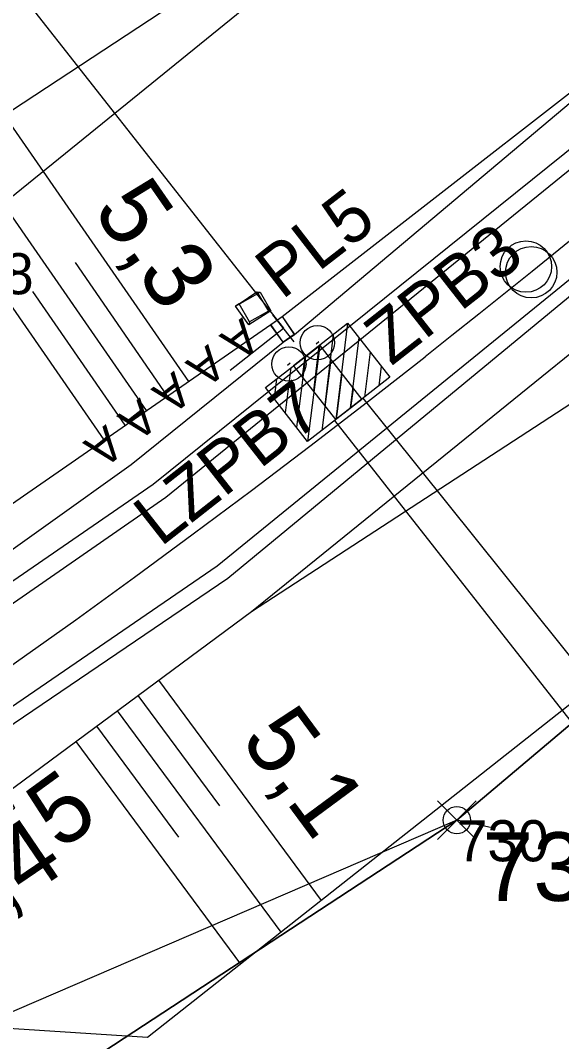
# Model space of a CAD drawing. Extents: x -800194 to -799078, y -1007177 to -1006597.
# Drawn here: x -799482.23 to -799466.45, y -1006953.32 to -1006923.53 of the extents above; entities that cross this region are included whole.
import ezdxf

# ---------------------------------------------------------------- set-up
doc = ezdxf.new("R2010")
doc.units = 0
for name, color, linetype in [('02_Osa_koleje', 7, 'Continuous'), ('_Vrstva 7 - Přesunutá', 7, 'Continuous'), ('Obvod stavby', 7, 'Continuous'), ('Vrstva 11', 7, 'Continuous'), ('Vrstva 12', 7, 'Continuous'), ('Vrstva 13', 7, 'Continuous'), ('Vrstva 27', 7, 'Continuous'), ('Vrstva 3', 7, 'Continuous'), ('Vrstva 4', 7, 'Continuous'), ('Vrstva 48', 7, 'Continuous'), ('Vrstva 49', 7, 'Continuous'), ('Vrstva 53', 7, 'Continuous'), ('Vrstva 55', 7, 'Continuous'), ('Vrstva 56', 7, 'Continuous'), ('Vrstva 6', 7, 'Continuous'), ('Vrstva 60', 7, 'Continuous'), ('Vrstva 7', 7, 'Continuous')]:
    doc.layers.add(name, color=color, linetype=linetype)

msp = doc.modelspace()

# ---------------------------------------------------------------- linework, layer by layer
at = {"layer": '02_Osa_koleje'}
msp.add_lwpolyline([(-799465.749, -1006929.588), (-799466.523, -1006930.22), (-799467.3, -1006930.85), (-799468.078, -1006931.478), (-799468.859, -1006932.103), (-799469.642, -1006932.726), (-799470.426, -1006933.345)], dxfattribs=at)
msp.add_arc((-799651.022, -1006703.891), 292, 255.62486, 308.20516, dxfattribs=at)
at = {"layer": '_Vrstva 7 - Přesunutá'}
msp.add_circle((-799467.33, -1006930.875), 0.75, dxfattribs=at)
at = {"layer": 'Obvod stavby'}
for p, q in [((-799470.066, -1006947.426), (-799468.934, -1006946.294)), ((-799470.066, -1006946.294), (-799468.934, -1006947.426))]:
    msp.add_line(p, q, dxfattribs=at)
msp.add_lwpolyline([(-799559.64, -1006968.48), (-799519.68, -1006952.01), (-799500.87, -1006940.41), (-799496.64, -1006937.8), (-799494.85, -1006936.7), (-799484.52, -1006930.32), (-799457.99, -1006908.8), (-799435, -1006885.17), (-799430.26, -1006880.27), (-799425.53, -1006875.38), (-799422.55, -1006864.36), (-799416.748, -1006858.798), (-799395.763, -1006879.374), (-799413.75, -1006898.23), (-799418.41, -1006902.53), (-799423.07, -1006906.83), (-799433.4, -1006916.39), (-799469.5, -1006946.86), (-799487.22, -1006958.47), (-799495.25, -1006963.74), (-799521.98, -1006977.8), (-799546.71, -1006987.83)], dxfattribs=at)
msp.add_circle((-799469.5, -1006946.86), 0.4, dxfattribs=at)
at = {"layer": 'Vrstva 12'}
for p, q in [((-799475.329, -1006931.448), (-799475.236, -1006931.455)), ((-799475.848, -1006931.802), (-799475.952, -1006931.866)), ((-799474.922, -1006932.004), (-799474.993, -1006932.013)), ((-799475.551, -1006932.322), (-799475.567, -1006932.408)), ((-799474.93, -1006932.406), (-799474.926, -1006932.405)), ((-799474.599, -1006932.171), (-799474.596, -1006932.171)), ((-799474.241, -1006932.695), (-799474.237, -1006932.694)), ((-799474.57, -1006932.917), (-799474.568, -1006932.916))]:
    msp.add_line(p, q, dxfattribs=at)
for points in [[(-799475.236, -1006931.455), (-799474.922, -1006932.004), (-799475.567, -1006932.408), (-799475.952, -1006931.866), (-799475.236, -1006931.455)], [(-799475.329, -1006931.448), (-799474.993, -1006932.013), (-799475.551, -1006932.322), (-799475.848, -1006931.802), (-799475.329, -1006931.448)], [(-799474.599, -1006932.171), (-799474.241, -1006932.695), (-799474.57, -1006932.917), (-799474.93, -1006932.406), (-799474.599, -1006932.171)], [(-799474.596, -1006932.171), (-799474.237, -1006932.694), (-799474.568, -1006932.916), (-799474.926, -1006932.405), (-799474.596, -1006932.171)]]:
    msp.add_lwpolyline(points, dxfattribs=at)
at = {"layer": 'Vrstva 27'}
for p, q in [((-799473.605, -1006932.963), (-799473.527, -1006932.901)), ((-799474.438, -1006933.585), (-799474.36, -1006933.523))]:
    msp.add_line(p, q, dxfattribs=at)
for centre in [(-799473.566, -1006932.932), (-799474.399, -1006933.554)]:
    msp.add_circle(centre, 0.5, dxfattribs=at)
at = {"layer": 'Vrstva 3'}
for p, q in [((-799472.686, -1006932.363), (-799473.025, -1006935.171)), ((-799473.103, -1006932.691), (-799473.352, -1006934.755)), ((-799473.499, -1006933.01), (-799473.857, -1006935.816)), ((-799473.521, -1006933.019), (-799473.68, -1006934.337)), ((-799472.359, -1006932.78), (-799472.608, -1006934.844)), ((-799473.918, -1006933.335), (-799474.181, -1006935.397)), ((-799472.031, -1006933.198), (-799472.19, -1006934.516)), ((-799473.938, -1006933.346), (-799474.007, -1006933.92)), ((-799473.175, -1006933.429), (-799473.438, -1006935.492)), ((-799471.704, -1006933.615), (-799471.773, -1006934.189)), ((-799474.338, -1006933.659), (-799474.506, -1006934.977)), ((-799472.85, -1006933.849), (-799473.018, -1006935.167)), ((-799474.757, -1006933.984), (-799474.83, -1006934.557)), ((-799472.525, -1006934.269), (-799472.599, -1006934.842)), ((-799442.19, -1006974.528), (-799473.063, -1006935.201))]:
    msp.add_line(p, q, dxfattribs=at)
for points in [[(-799471.451, -1006933.937), (-799473.025, -1006935.171), (-799474.26, -1006933.598), (-799472.686, -1006932.363)], [(-799472.275, -1006934.592), (-799473.857, -1006935.816), (-799475.081, -1006934.234), (-799473.499, -1006933.01)]]:
    msp.add_lwpolyline(points, close=True, dxfattribs=at)
msp.add_lwpolyline([(-799439.356, -1006972.379), (-799450.062, -1006959.03), (-799451.608, -1006960.27), (-799472.235, -1006934.552)], dxfattribs=at)
at = {"layer": 'Vrstva 4'}
for points in [[(-799510.394, -1006958.536), (-799498.027, -1006951.328), (-799477.988, -1006937.435), (-799460.33, -1006923.117), (-799451.862, -1006915.581), (-799443.604, -1006907.9), (-799435.444, -1006900.067), (-799428.64, -1006893.299), (-799422.817, -1006887.511), (-799415.998, -1006880.595), (-799408.158, -1006872.652), (-799401.02, -1006864.85)], [(-799509.248, -1006960.724), (-799497.456, -1006953.809), (-799476.495, -1006939.437), (-799458.707, -1006924.982), (-799450.277, -1006917.43), (-799441.932, -1006909.717), (-799433.783, -1006901.867), (-799426.9, -1006895.092), (-799421.037, -1006889.182), (-799414.218, -1006882.281), (-799406.443, -1006874.417), (-799398.609, -1006866.93)], [(-799511.236, -1006957.129), (-799499.236, -1006950.771), (-799498.598, -1006949.914), (-799498.679, -1006949.705), (-799496.151, -1006948.479), (-799496.251, -1006948.258), (-799490.687, -1006944.683), (-799490.497, -1006944.878), (-799488.249, -1006943.052), (-799488.105, -1006943.216), (-799486.269, -1006941.68), (-799478.997, -1006936.484), (-799474.568, -1006932.916), (-799474.237, -1006932.694), (-799461.519, -1006921.99), (-799452.935, -1006914.372), (-799444.695, -1006906.886), (-799436.579, -1006898.932), (-799429.629, -1006892.192), (-799429.07, -1006892.727), (-799423.479, -1006886.901), (-799416.56, -1006880.007), (-799417.085, -1006879.46), (-799415.349, -1006878.386)], [(-799510.726, -1006958.045), (-799497.901, -1006950.516), (-799478.36, -1006937.055), (-799461.534, -1006923.53), (-799452.128, -1006915.305), (-799443.894, -1006907.632), (-799435.739, -1006899.754), (-799428.922, -1006893.007), (-799423.223, -1006887.256), (-799416.277, -1006880.269), (-799414.896, -1006878.87)], [(-799509.087, -1006961.127), (-799497.277, -1006954.118), (-799476.183, -1006939.802), (-799458.586, -1006925.284), (-799449.914, -1006917.869), (-799441.499, -1006910.139), (-799433.371, -1006902.28), (-799426.451, -1006895.478), (-799420.657, -1006889.585), (-799413.85, -1006882.742), (-799412.388, -1006881.287)], [(-799507.817, -1006962.779), (-799497.104, -1006956.83), (-799497.4, -1006955.599), (-799497.585, -1006955.395), (-799495.628, -1006953.965), (-799495.505, -1006954.146), (-799493.236, -1006952.753), (-799493.081, -1006952.976), (-799487.499, -1006949.378), (-799487.565, -1006949.124), (-799485.713, -1006947.881), (-799485.847, -1006947.698), (-799483.858, -1006946.36), (-799483.734, -1006946.536), (-799483.686, -1006946.569), (-799482.647, -1006946.068), (-799475.489, -1006940.774), (-799457.684, -1006926.366)]]:
    msp.add_lwpolyline(points, dxfattribs=at)
at = {"layer": 'Vrstva 48'}
for p, q in [((-799477.319, -1006934.06), (-799482.69, -1006926.295)), ((-799478.552, -1006934.913), (-799483.943, -1006927.119)), ((-799479.786, -1006935.767), (-799485.197, -1006927.943)), ((-799477.935, -1006934.487), (-799480.626, -1006930.597)), ((-799479.169, -1006935.34), (-799481.87, -1006931.436)), ((-799478.201, -1006942.78), (-799473.453, -1006949.2)), ((-799478.804, -1006943.226), (-799476.423, -1006946.446)), ((-799479.407, -1006943.672), (-799474.631, -1006950.13)), ((-799480.01, -1006944.118), (-799477.616, -1006947.356)), ((-799480.613, -1006944.564), (-799475.81, -1006951.059))]:
    msp.add_line(p, q, dxfattribs=at)
at = {"layer": 'Vrstva 49'}
for points in [[(-799429.125, -1006891.656), (-799433.133, -1006889.484), (-799437.572, -1006888.963), (-799439.693, -1006890.332), (-799461.15, -1006912.135), (-799487.142, -1006929.222), (-799487.006, -1006931.546), (-799490.308, -1006935.771)], [(-799490.09, -1006944.145), (-799488.194, -1006942.597), (-799488.011, -1006942.815), (-799488.011, -1006942.815), (-799486.419, -1006941.508), (-799486.269, -1006941.68), (-799484.618, -1006939.109), (-799474.926, -1006932.405), (-799474.596, -1006932.171), (-799461.519, -1006921.99), (-799452.935, -1006914.372), (-799445.566, -1006906.106), (-799432.588, -1006892.596), (-799429.125, -1006891.656)], [(-799486.865, -1006949.018), (-799484.86, -1006947.727), (-799485.016, -1006947.459), (-799485.713, -1006947.881), (-799483.734, -1006946.536), (-799483.686, -1006946.569), (-799483.396, -1006947.063), (-799482.389, -1006946.51), (-799482.647, -1006946.068), (-799475.489, -1006940.774), (-799464.892, -1006933.871), (-799456.989, -1006927.138), (-799455.117, -1006925.642), (-799440.165, -1006911.165), (-799428.918, -1006899.95), (-799428.299, -1006900.544), (-799427.466, -1006899.73), (-799428.131, -1006899.117), (-799426.509, -1006898.237), (-799425.17, -1006895.342)], [(-799423.903, -1006906.911), (-799427.313, -1006910.033), (-799439.866, -1006919.177), (-799453.667, -1006933.596), (-799478.523, -1006953.199), (-799482.72, -1006952.931), (-799486.865, -1006949.018)]]:
    msp.add_lwpolyline(points, dxfattribs=at)
at = {"layer": 'Vrstva 53'}
for points in [[(-799559.64, -1006968.48), (-799519.68, -1006952.01), (-799500.87, -1006940.41), (-799496.64, -1006937.8), (-799494.85, -1006936.7), (-799484.519, -1006930.319), (-799457.99, -1006908.8), (-799435, -1006885.17), (-799430.26, -1006880.27), (-799425.53, -1006875.38), (-799422.55, -1006864.36), (-799390.88, -1006834), (-799358.35, -1006806.65), (-799352.29, -1006801.56), (-799330.91, -1006783.58), (-799314.235, -1006766.649)], [(-799312.398, -1006791.976), (-799331.37, -1006811.87), (-799413.75, -1006898.23), (-799418.41, -1006902.53), (-799423.07, -1006906.83), (-799433.4, -1006916.39), (-799469.5, -1006946.86), (-799487.22, -1006958.47), (-799495.25, -1006963.74), (-799521.98, -1006977.8), (-799546.71, -1006987.83)]]:
    msp.add_lwpolyline(points, dxfattribs=at)
at = {"layer": 'Vrstva 55'}
for points in [[(-799494.85, -1006936.7), (-799484.52, -1006930.32), (-799457.99, -1006908.8), (-799435, -1006885.17)], [(-799487.22, -1006958.47), (-799469.5, -1006946.86), (-799433.4, -1006916.39)]]:
    msp.add_lwpolyline(points, dxfattribs=at)
at = {"layer": 'Vrstva 56'}
for p, q in [((-799469.5, -1006946.86), (-799483.5, -1006952.89)), ((-799468.522, -1006947.069), (-799469.5, -1006946.861))]:
    msp.add_line(p, q, dxfattribs=at)
at = {"layer": 'Vrstva 6'}
for p, q in [((-799505.431, -1006893.183), (-799474.557, -1006932.512)), ((-799474.248, -1006932.905), (-799474.866, -1006932.119)), ((-799476.114, -1006933.735), (-799474.557, -1006932.512))]:
    msp.add_line(p, q, dxfattribs=at)
at = {"layer": 'Vrstva 60'}
msp.add_line((-799469.5, -1006946.86), (-799469.5, -1006946.86), dxfattribs=at)
at = {"layer": 'Vrstva 7'}
msp.add_circle((-799467.486, -1006930.71), 0.75, dxfattribs=at)

# ---------------------------------------------------------------- texts
at = {"layer": 'Obvod stavby'}
msp.add_text('730', height=2, rotation=360, dxfattribs=at).set_placement((-799468.761, -1006949.214))
at = {"layer": 'Vrstva 11'}
msp.add_text('5', height=2, rotation=36.0719, dxfattribs=at).set_placement((-799481.069, -1006947.768))
at = {"layer": 'Vrstva 13'}
msp.add_text('0,4', height=2, rotation=34.2014, dxfattribs=at).set_placement((-799483.93, -1006950.409))
at = {"layer": 'Vrstva 27'}
for s, p in [('ZPB3', (-799471.413, -1006933.627)), ('LZPB7', (-799478.141, -1006938.908))]:
    msp.add_text(s, height=1.5, rotation=38.1328, dxfattribs=at).set_placement(p)
at = {"layer": 'Vrstva 48'}
for s, rotation, p in [('5,3', 304.6718, (-799480.14, -1006929.068)), ('5,1', 306.4863, (-799475.838, -1006944.522))]:
    msp.add_text(s, height=2, rotation=rotation, dxfattribs=at).set_placement(p)
at = {"layer": 'Vrstva 6'}
for s, height, rotation, p in [('PL5', 1.5, 37.7253, (-799474.604, -1006931.701)), ('  A A A A A ', 1, 218.1328, (-799475.174, -1006931.725))]:
    msp.add_text(s, height=height, rotation=rotation, dxfattribs=at).set_placement(p)
at = {"layer": 'Vrstva 60'}
for s, p in [('718', (-799484.52, -1006931.52)), ('730', (-799469.5, -1006948.06))]:
    msp.add_text(s, height=1.2, dxfattribs=at).set_placement(p)

doc.saveas('drawing.dxf')
